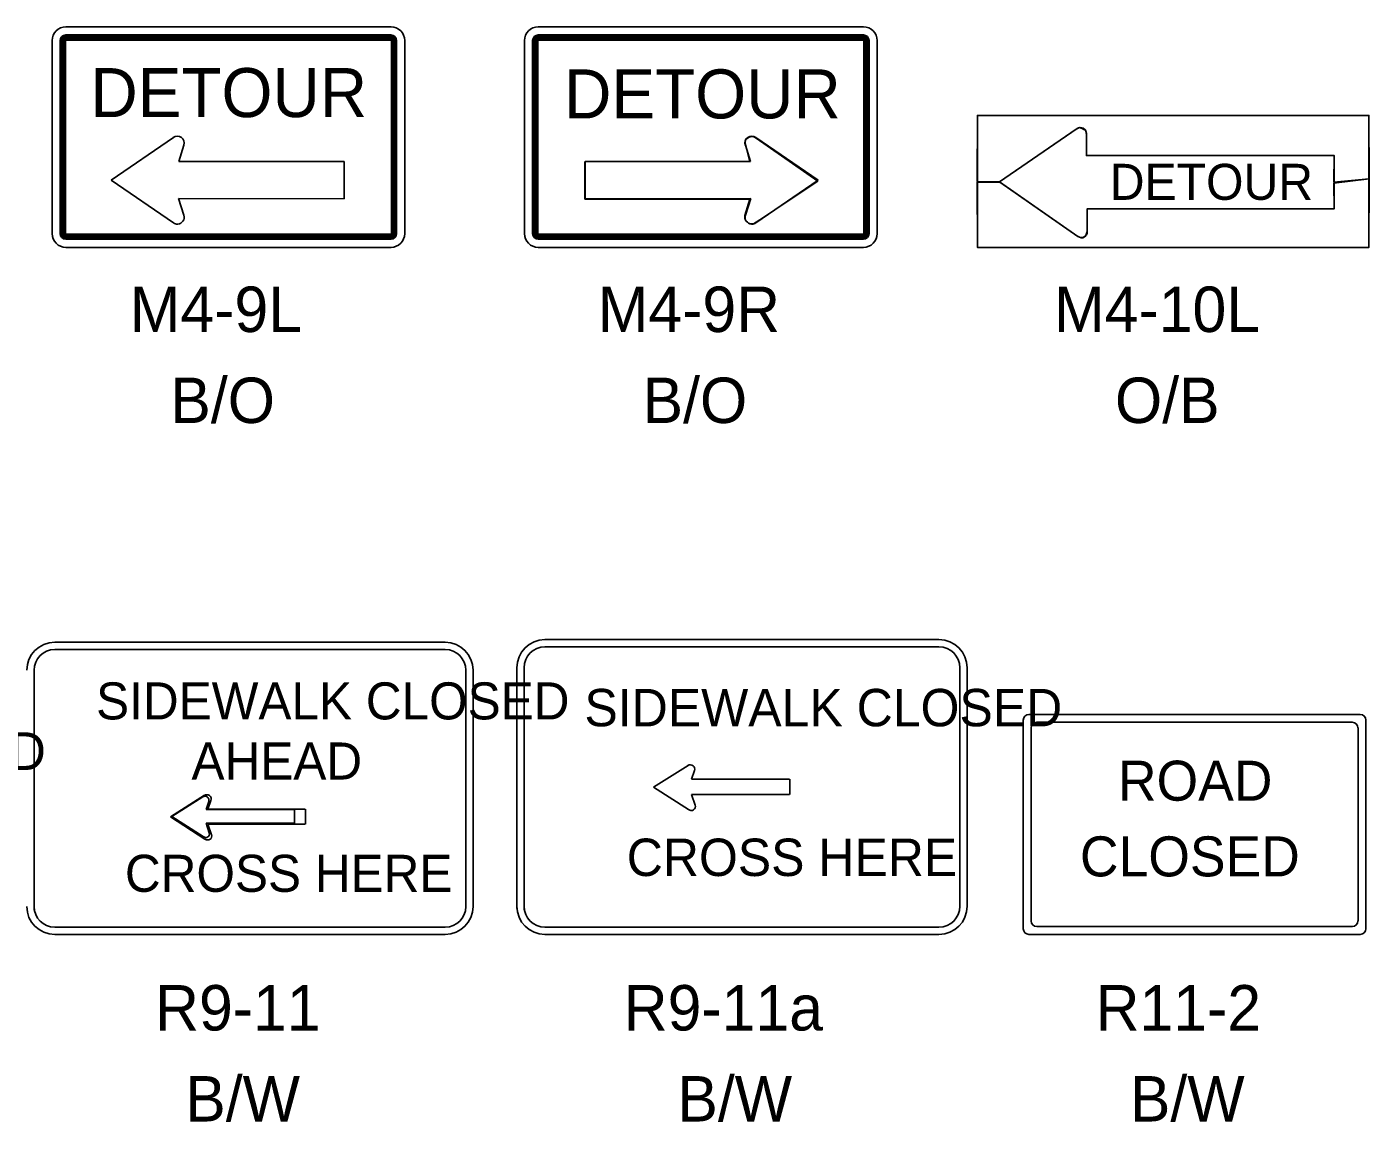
# Model space of a CAD drawing. Extents: x 10034 to 10794, y 10044 to 10499.
# Drawn here: x 10288.5 to 10391.9, y 10408.8 to 10493.1 of the extents above; entities that cross this region are included whole.
import ezdxf

# ---------------------------------------------------------------- set-up
doc = ezdxf.new("R2010")
doc.units = 0
for name, color, linetype in [('DSDate', 7, 'Continuous'), ('DSIndex', 7, 'Continuous'), ('DSText', 7, 'Continuous'), ('PlotBorder_dp', 7, 'Continuous')]:
    doc.layers.add(name, color=color, linetype=linetype)

msp = doc.modelspace()

# ---------------------------------------------------------------- linework, layer by layer
at = {"layer": 'DSDate'}
for p, q in [((10366.31, 10439.57), (10390.62, 10439.57)), ((10365.87, 10436.33), (10365.87, 10439.13)), ((10391.06, 10439.13), (10391.06, 10436.17)), ((10365.87, 10424.28), (10365.87, 10436.38)), ((10391.06, 10436.38), (10391.06, 10424.28)), ((10390.62, 10423.84), (10366.31, 10423.84))]:
    msp.add_line(p, q, dxfattribs=at)
for centre, start, end in [((10366.31, 10439.13), 90, 180), ((10390.61, 10439.13), 0, 90), ((10366.31, 10424.28), 180, 270), ((10390.61, 10424.28), 270, 0)]:
    msp.add_arc(centre, 0.44, start, end, dxfattribs=at)
at = {"layer": 'DSIndex'}
for p, q in [((10316.55, 10493.13), (10291.49, 10493.13)), ((10316.55, 10492.51), (10291.49, 10492.51)), ((10316.55, 10492.44), (10291.49, 10492.44)), ((10316.55, 10492.37), (10291.49, 10492.37)), ((10316.55, 10492.3), (10291.49, 10492.3)), ((10316.55, 10492.24), (10291.49, 10492.24)), ((10316.55, 10492.17), (10291.49, 10492.17)), ((10327.89, 10493.13), (10352.94, 10493.13)), ((10327.89, 10492.51), (10352.94, 10492.51)), ((10327.89, 10492.44), (10352.94, 10492.44)), ((10327.89, 10492.37), (10352.94, 10492.37)), ((10327.89, 10492.3), (10352.94, 10492.3)), ((10327.89, 10492.24), (10352.94, 10492.24)), ((10327.89, 10492.17), (10352.94, 10492.17)), ((10290.43, 10492.07), (10290.43, 10477.21)), ((10291.06, 10492.07), (10291.06, 10477.21)), ((10291.12, 10492.07), (10291.12, 10477.21)), ((10291.19, 10492.07), (10291.19, 10477.21)), ((10291.26, 10492.07), (10291.26, 10477.21)), ((10291.32, 10492.07), (10291.32, 10477.21)), ((10291.39, 10492.07), (10291.39, 10477.21)), ((10291.46, 10492.07), (10291.46, 10477.21)), ((10316.55, 10492.11), (10291.49, 10492.11)), ((10316.58, 10477.21), (10316.58, 10492.07)), ((10316.65, 10477.21), (10316.65, 10492.07)), ((10316.71, 10477.21), (10316.71, 10492.07)), ((10316.78, 10477.21), (10316.78, 10492.07)), ((10316.85, 10477.21), (10316.85, 10492.07)), ((10316.92, 10477.21), (10316.92, 10492.07)), ((10316.98, 10477.21), (10316.98, 10492.07)), ((10317.61, 10477.21), (10317.61, 10492.07)), ((10326.83, 10477.21), (10326.83, 10492.07)), ((10327.45, 10477.21), (10327.45, 10492.07)), ((10327.52, 10477.21), (10327.52, 10492.07)), ((10327.59, 10477.21), (10327.59, 10492.07)), ((10327.66, 10477.21), (10327.66, 10492.07)), ((10327.72, 10477.21), (10327.72, 10492.07)), ((10327.79, 10477.21), (10327.79, 10492.07)), ((10327.85, 10477.21), (10327.85, 10492.07)), ((10327.89, 10492.11), (10352.94, 10492.11)), ((10352.98, 10492.07), (10352.98, 10477.21)), ((10353.05, 10492.07), (10353.05, 10477.21)), ((10353.11, 10492.07), (10353.11, 10477.21)), ((10353.18, 10492.07), (10353.18, 10477.21)), ((10353.25, 10492.07), (10353.25, 10477.21)), ((10353.32, 10492.07), (10353.32, 10477.21)), ((10353.38, 10492.07), (10353.38, 10477.21)), ((10354, 10492.07), (10354, 10477.21)), ((10361.73, 10476.15), (10361.73, 10486.31)), ((10361.73, 10486.31), (10391.9, 10486.31)), ((10391.9, 10486.31), (10391.9, 10476.15)), ((10363.42, 10481.2), (10369.42, 10485.3)), ((10370.13, 10483.22), (10370.13, 10484.92)), ((10294.99, 10481.33), (10299.78, 10484.62)), ((10300.59, 10484.03), (10300.19, 10482.76)), ((10343.85, 10484.03), (10344.25, 10482.76)), ((10349.45, 10481.33), (10344.66, 10484.62)), ((10370.13, 10483.22), (10389.23, 10483.22)), ((10389.23, 10479.12), (10389.23, 10483.22)), ((10300.19, 10482.76), (10312.93, 10482.76)), ((10312.93, 10482.76), (10312.93, 10479.9)), ((10344.25, 10482.76), (10331.51, 10482.76)), ((10331.51, 10482.76), (10331.51, 10479.9)), ((10299.78, 10478.04), (10294.99, 10481.33)), ((10344.66, 10478.03), (10349.45, 10481.33)), ((10363.42, 10481.2), (10369.48, 10476.98)), ((10312.93, 10479.9), (10300.18, 10479.91)), ((10300.18, 10479.91), (10300.58, 10478.63)), ((10331.51, 10479.9), (10344.26, 10479.91)), ((10344.26, 10479.91), (10343.85, 10478.63)), ((10370.19, 10479.12), (10389.23, 10479.12)), ((10370.19, 10479.12), (10370.19, 10477.36)), ((10291.49, 10477.17), (10316.55, 10477.17)), ((10291.49, 10477.11), (10316.55, 10477.11)), ((10291.49, 10477.04), (10316.55, 10477.04)), ((10291.49, 10476.97), (10316.55, 10476.97)), ((10291.49, 10476.9), (10316.55, 10476.9)), ((10291.49, 10476.84), (10316.55, 10476.84)), ((10291.49, 10476.77), (10316.55, 10476.77)), ((10352.94, 10477.17), (10327.89, 10477.17)), ((10352.94, 10477.11), (10327.89, 10477.11)), ((10352.94, 10477.04), (10327.89, 10477.04)), ((10352.94, 10476.97), (10327.89, 10476.97)), ((10352.94, 10476.9), (10327.89, 10476.9)), ((10352.94, 10476.84), (10327.89, 10476.84)), ((10352.94, 10476.77), (10327.89, 10476.77)), ((10291.49, 10476.15), (10316.55, 10476.15)), ((10352.94, 10476.15), (10327.89, 10476.15)), ((10391.9, 10476.15), (10361.73, 10476.15)), ((10336.78, 10434.57), (10339.43, 10436.25)), ((10339.93, 10435.85), (10339.7, 10435.18)), ((10339.47, 10432.84), (10336.78, 10434.57)), ((10339.7, 10435.18), (10347.26, 10435.18)), ((10347.28, 10435.18), (10347.28, 10434)), ((10299.55, 10432.28), (10302.17, 10433.95)), ((10299.55, 10432.28), (10302.17, 10433.95)), ((10299.66, 10432.31), (10302.04, 10433.82)), ((10299.66, 10432.31), (10302.04, 10433.82)), ((10302.04, 10433.82), (10299.66, 10432.31)), ((10302.5, 10433.47), (10302.29, 10432.86)), ((10302.67, 10433.55), (10302.44, 10432.89)), ((10302.67, 10433.55), (10302.44, 10432.89)), ((10347.26, 10434), (10339.7, 10434)), ((10339.7, 10434), (10339.97, 10433.18)), ((10302.21, 10430.57), (10299.55, 10432.28)), ((10302.21, 10430.57), (10299.55, 10432.28)), ((10302.08, 10430.76), (10299.66, 10432.31)), ((10302.29, 10432.86), (10309.1, 10432.86)), ((10302.44, 10432.89), (10309.93, 10432.89)), ((10302.44, 10432.89), (10309.93, 10432.89)), ((10309.12, 10432.86), (10309.12, 10431.8)), ((10309.95, 10432.89), (10309.95, 10431.72)), ((10309.95, 10432.89), (10309.95, 10431.72)), ((10309.1, 10431.8), (10302.29, 10431.8)), ((10302.29, 10431.8), (10302.54, 10431.06)), ((10309.93, 10431.72), (10302.44, 10431.72)), ((10302.44, 10431.72), (10302.71, 10430.91)), ((10309.93, 10431.72), (10302.44, 10431.72)), ((10302.44, 10431.72), (10302.71, 10430.91))]:
    msp.add_line(p, q, dxfattribs=at)
for points in [[(10363.42, 10481.2), (10361.71, 10481.23), (10361.73, 10486.31), (10391.9, 10486.31), (10391.92, 10481.42), (10389.2, 10481.16), (10389.23, 10483.22), (10370.13, 10483.22), (10370.13, 10484.92), (10370.06, 10485.17), (10369.93, 10485.24), (10369.8, 10485.3), (10369.6, 10485.37), (10369.35, 10485.25)], [(10344.2, 10482.76), (10331.48, 10482.74), (10331.48, 10479.87), (10344.2, 10479.87), (10343.82, 10478.6), (10343.82, 10478.39), (10343.87, 10478.24), (10344.08, 10478.02), (10344.29, 10477.97), (10344.47, 10477.97), (10344.68, 10478.08), (10344.96, 10478.27), (10349.43, 10481.26), (10344.68, 10484.55), (10344.5, 10484.66), (10344.33, 10484.68), (10344.15, 10484.64), (10343.87, 10484.47), (10343.84, 10484.17)], [(10363.46, 10481.16), (10361.71, 10481.16), (10361.73, 10476.15), (10391.9, 10476.15), (10391.92, 10481.42), (10389.2, 10481.1), (10389.23, 10479.12), (10370.19, 10479.12), (10370.19, 10477.36), (10370.12, 10477.15), (10370.06, 10477.02), (10369.99, 10476.96), (10369.86, 10476.89), (10369.73, 10476.89), (10369.48, 10476.98)]]:
    msp.add_lwpolyline(points, close=True, dxfattribs=at)
for points in [[(10320.72, 10445.73), (10290.63, 10445.73)], [(10358.77, 10445.94), (10328.4, 10445.94)], [(10320.72, 10445.18), (10290.63, 10445.18)], [(10358.77, 10445.38), (10328.4, 10445.38)], [(10289.04, 10443.58), (10289.04, 10425.11)], [(10322.31, 10425.41), (10322.31, 10443.58)], [(10322.87, 10425.41), (10322.87, 10443.58)], [(10326.24, 10443.77), (10326.24, 10425.23)], [(10326.8, 10443.77), (10326.8, 10425.12)], [(10360.38, 10425.43), (10360.38, 10443.77)], [(10360.94, 10425.43), (10360.94, 10443.77)], [(10290.63, 10423.79), (10320.72, 10423.79)], [(10290.63, 10423.23), (10320.72, 10423.23)], [(10328.4, 10423.79), (10358.77, 10423.79)], [(10328.4, 10423.23), (10358.77, 10423.23)]]:
    msp.add_lwpolyline(points, dxfattribs=at)
for centre, radius, start, end in [((10291.49, 10492.07), 1.06, 90, 180), ((10291.49, 10492.07), 0.437, 90.2222, 179.7773), ((10291.49, 10492.07), 0.37, 90.2621, 179.7371), ((10291.49, 10492.07), 0.303, 90.3197, 179.6792), ((10291.49, 10492.07), 0.236, 90.4096, 179.5885), ((10291.49, 10492.07), 0.17, 90.5691, 179.4264), ((10291.49, 10492.07), 0.103, 90.9343, 179.0534), ((10316.54, 10492.07), 1.06, 0.088, 89.912), ((10316.54, 10492.07), 0.437, 0.2227, 89.7773), ((10316.54, 10492.07), 0.37, 0.2629, 89.7371), ((10316.54, 10492.07), 0.303, 0.3208, 89.6792), ((10316.54, 10492.07), 0.236, 0.4115, 89.5885), ((10316.54, 10492.07), 0.17, 0.5736, 89.4264), ((10316.54, 10492.07), 0.103, 0.9466, 89.0534), ((10327.89, 10492.07), 1.06, 90.088, 179.912), ((10327.89, 10492.07), 0.437, 90.2227, 179.7773), ((10327.89, 10492.07), 0.37, 90.2629, 179.7371), ((10327.89, 10492.07), 0.303, 90.3208, 179.6792), ((10327.89, 10492.07), 0.236, 90.4115, 179.5885), ((10327.89, 10492.07), 0.17, 90.5736, 179.4264), ((10327.89, 10492.07), 0.103, 90.9466, 179.0534), ((10352.94, 10492.07), 1.06, 0, 90), ((10352.94, 10492.07), 0.437, 0.2227, 89.7778), ((10352.94, 10492.07), 0.37, 0.2629, 89.7379), ((10352.94, 10492.07), 0.303, 0.3208, 89.6803), ((10352.94, 10492.07), 0.236, 0.4115, 89.5904), ((10352.94, 10492.07), 0.17, 0.5736, 89.4309), ((10352.94, 10492.07), 0.103, 0.9466, 89.0657), ((10291.49, 10492.07), 0.0359, 92.7057, 177.2943), ((10316.54, 10492.07), 0.0359, 2.7057, 87.2943), ((10327.89, 10492.07), 0.0359, 92.7057, 177.2943), ((10352.94, 10492.07), 0.0359, 2.7057, 87.2943), ((10369.67, 10484.92), 0.453, 0, 124.3372), ((10300.08, 10484.19), 0.531, 342.0875, 125.7703), ((10344.35, 10484.19), 0.531, 54.2297, 197.9125), ((10300.08, 10478.47), 0.531, 235.5481, 273.8506), ((10300.08, 10478.47), 0.531, 274.008, 16.4677), ((10344.36, 10478.47), 0.531, 163.5323, 265.992), ((10344.36, 10478.47), 0.531, 266.1494, 304.4519), ((10291.49, 10477.21), 1.06, 180, 270), ((10291.49, 10477.21), 0.437, 180.2222, 269.7773), ((10291.49, 10477.21), 0.37, 180.2627, 269.7371), ((10291.49, 10477.21), 0.303, 180.3205, 269.6792), ((10291.49, 10477.21), 0.236, 180.411, 269.5885), ((10291.49, 10477.21), 0.17, 180.5727, 269.4264), ((10291.49, 10477.21), 0.103, 180.9417, 269.0534), ((10316.54, 10477.21), 1.06, 270, 0), ((10316.54, 10477.21), 0.437, 270.2227, 359.7773), ((10316.54, 10477.21), 0.37, 270.2629, 359.7371), ((10316.54, 10477.21), 0.303, 270.3208, 359.6792), ((10316.54, 10477.21), 0.236, 270.4115, 359.5885), ((10316.54, 10477.21), 0.17, 270.5736, 359.4264), ((10316.54, 10477.21), 0.103, 270.9466, 359.0534), ((10327.89, 10477.21), 1.06, 180, 270), ((10327.89, 10477.21), 0.437, 180.2227, 269.7773), ((10327.89, 10477.21), 0.37, 180.2629, 269.7371), ((10327.89, 10477.21), 0.303, 180.3208, 269.6792), ((10327.89, 10477.21), 0.236, 180.4115, 269.5885), ((10327.89, 10477.21), 0.17, 180.5736, 269.4264), ((10327.89, 10477.21), 0.103, 180.9466, 269.0534), ((10352.94, 10477.21), 1.06, 270, 0), ((10352.94, 10477.21), 0.437, 270.2227, 359.7778), ((10352.94, 10477.21), 0.37, 270.2629, 359.7373), ((10352.94, 10477.21), 0.303, 270.3208, 359.6795), ((10352.94, 10477.21), 0.236, 270.4115, 359.589), ((10352.94, 10477.21), 0.17, 270.5736, 359.4273), ((10352.94, 10477.21), 0.103, 270.9466, 359.0583), ((10369.74, 10477.36), 0.453, 235.1755, 0), ((10290.63, 10443.58), 2.15, 90, 180), ((10320.72, 10443.58), 2.15, 360, 90), ((10328.41, 10443.77), 2.17, 90, 180), ((10358.77, 10443.77), 2.17, 360, 90), ((10290.63, 10443.58), 1.59, 90, 180), ((10320.72, 10443.58), 1.59, 360, 90), ((10328.41, 10443.77), 1.61, 90, 180), ((10358.77, 10443.77), 1.61, 360, 90), ((10290.63, 10425.38), 2.15, 180, 270), ((10290.63, 10425.38), 1.59, 180, 270), ((10320.72, 10425.38), 2.15, 270, 360), ((10320.72, 10425.38), 1.59, 270, 360), ((10328.41, 10425.4), 2.17, 180, 270), ((10328.41, 10425.4), 1.61, 180, 270), ((10358.77, 10425.4), 2.17, 270, 360), ((10358.77, 10425.4), 1.61, 270, 360)]:
    msp.add_arc(centre, radius, start, end, dxfattribs=at)
for centre, major_axis, ratio, start_param, end_param in [((10291.49, 10477.21), (0, -0.0425), 0.8464, 4.751773, 6.235961), ((10316.54, 10477.21), (0, 0.0425), 0.8464, 3.188817, 4.67241), ((10327.89, 10477.21), (0, -0.0425), 0.8464, 4.752368, 6.235961), ((10352.94, 10477.21), (0, 0.0425), 0.8464, 3.188816, 4.673005), ((10339.61, 10435.96), (0.344, 0), 0.967097, 5.956778, 8.424186), ((10302.21, 10433.57), (0.31, 0), 0.967097, 5.956778, 8.424186), ((10302.35, 10433.66), (0.341, 0), 0.967097, 5.956778, 8.424186), ((10302.35, 10433.66), (0.341, 0), 0.967097, 5.956778, 8.424186), ((10339.68, 10433.08), (0.32, 0), 0.967097, 3.98718, 6.638521), ((10302.27, 10430.97), (0.288, 0), 0.967097, 3.98718, 6.638521), ((10302.42, 10430.81), (0.317, 0), 0.967097, 3.98718, 6.638521), ((10302.42, 10430.81), (0.317, 0), 0.967097, 3.98718, 6.638521)]:
    msp.add_ellipse(centre, major_axis=major_axis, ratio=ratio, start_param=start_param, end_param=end_param, dxfattribs=at)
at = {"layer": 'DSText'}
for p, q in [((10365.26, 10436.29), (10365.26, 10439.74)), ((10365.7, 10440.18), (10391.23, 10440.18)), ((10391.67, 10439.74), (10391.67, 10436.26)), ((10365.26, 10423.67), (10365.26, 10436.38)), ((10391.67, 10436.38), (10391.67, 10423.67)), ((10391.23, 10423.23), (10365.7, 10423.23))]:
    msp.add_line(p, q, dxfattribs=at)
for centre, start, end in [((10365.7, 10439.74), 90, 180), ((10391.23, 10439.74), 0, 90), ((10365.7, 10423.67), 180, 270), ((10391.23, 10423.67), 270, 360)]:
    msp.add_arc(centre, 0.44, start, end, dxfattribs=at)

# ---------------------------------------------------------------- texts
at = {"layer": 'DSIndex'}
for s, height, p in [('DETOUR', 3.777, (10293.38, 10486.18)), ('DETOUR', 3.777, (10329.88, 10486.08)), ('DETOUR', 2.774, (10371.93, 10479.81)), ('M4-9L', 3.5, (10296.42, 10469.63)), ('M4-9R', 3.5, (10332.48, 10469.63)), ('M4-10L', 3.5, (10367.64, 10469.63)), ('B/O', 3.5, (10299.54, 10462.62)), ('B/O', 3.5, (10335.93, 10462.62)), ('O/B', 3.5, (10372.33, 10462.62)), ('SIDEWALK CLOSED', 2.8539, (10293.82, 10439.79)), ('SIDEWALK CLOSED', 2.8804, (10331.45, 10439.26)), ('SIDEWALK CLOSED', 2.8971, (10252.92, 10435.9)), ('AHEAD', 2.854, (10301.17, 10435.16)), ('CROSS HERE', 2.88, (10334.71, 10427.73)), ('CROSS HERE', 2.854, (10296.04, 10426.51)), ('R9-11', 3.5, (10298.37, 10415.83)), ('R9-11a', 3.5, (10334.48, 10415.83)), ('B/W', 3.5, (10300.69, 10408.82)), ('B/W', 3.5, (10338.61, 10408.82))]:
    msp.add_text(s, height=height, dxfattribs=at).set_placement(p)
at = {"layer": 'PlotBorder_dp'}
for s, height, p in [('ROAD', 3.081, (10372.56, 10433.53)), ('CLOSED', 3.081, (10369.63, 10427.7)), ('R11-2', 3.5, (10370.84, 10415.83)), ('B/W', 3.5, (10373.48, 10408.82))]:
    msp.add_text(s, height=height, dxfattribs=at).set_placement(p)

doc.saveas('drawing.dxf')
